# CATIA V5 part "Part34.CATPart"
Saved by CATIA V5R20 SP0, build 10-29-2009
Part number: 9AE052430-2
Revision: ANY
Definition: UNKNOWN
Nomenclature: 9AE052430-2
Source: Unknown
Bounding box of the stored display mesh (mm): x -16.827 to 16.827, y 0 to 44, z -17 to 17
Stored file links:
  C:\Users\Utente\Desktop\IO LAVORO\3D X SITO CF\CUMSA\3D files AE\AE 062430\Part34.CATPart
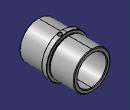
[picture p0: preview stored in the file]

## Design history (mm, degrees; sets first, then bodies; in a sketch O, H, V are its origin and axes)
Body1 "Cortar-Extruir1" (main body)
  Solid1: solid without history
